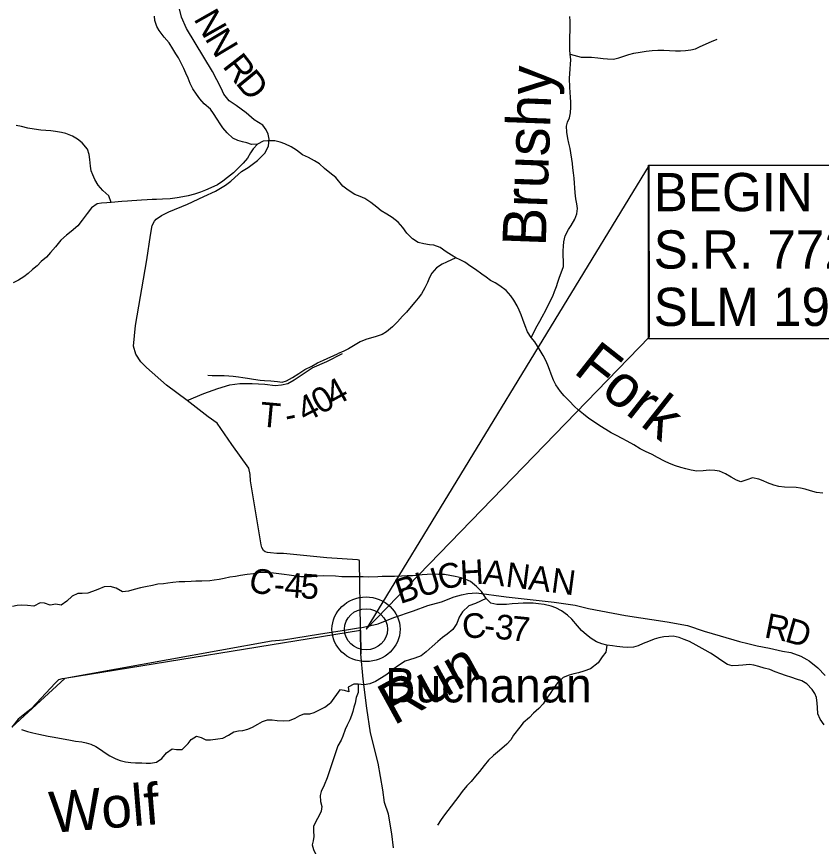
# Model space of a CAD drawing. Extents: x -139 to 835, y 0 to 440.
# Drawn here: x 183.8 to 242.7, y 229.6 to 290.4 of the extents above; entities that cross this region are included whole.
import ezdxf

# ---------------------------------------------------------------- set-up
doc = ezdxf.new("R2010")
doc.units = 0
for name, color, linetype in [('Default', 7, 'Continuous'), ('GM_X_County_Road', 7, 'Continuous'), ('GM_X_County_Road_Text', 7, 'Continuous'), ('GM_X_Major_River', 7, 'Continuous'), ('GM_X_Minor_River', 7, 'Continuous'), ('GM_X_Minor_River_Text', 7, 'Continuous'), ('GM_X_State_Route', 7, 'Continuous'), ('GM_X_Township_Road', 7, 'Continuous'), ('GM_X_Township_Road_Text', 7, 'Continuous'), ('GM_X_Unincorporated', 7, 'Continuous'), ('GM_X_Unincorporated_Location', 7, 'Continuous'), ('GM_X_Unincorporated_Text', 7, 'Continuous'), ('SH_Text', 7, 'Continuous')]:
    doc.layers.add(name, color=color, linetype=linetype)

msp = doc.modelspace()

# ---------------------------------------------------------------- linework, layer by layer
at = {"layer": 'Default'}
for p, q in [((208.941, 245.405), (187.302, 241.902)), ((208.941, 245.405), (187.302, 241.902)), ((208.941, 245.405), (208.975, 243.698)), ((187.302, 241.902), (183.419, 238.323))]:
    msp.add_line(p, q, dxfattribs=at)
at = {"layer": 'GM_X_County_Road'}
for points in [[(208.938, 245.595), (208.877, 250.478), (208.839, 250.551), (208.723, 250.588), (206.492, 250.734), (203.319, 251.036), (202.825, 251.041), (202.369, 251.082), (202.141, 251.108), (201.964, 251.171), (201.852, 251.256), (201.727, 251.475), (201.679, 251.668), (200.909, 256.37), (200.863, 256.816), (200.78, 257.288), (199.532, 259.026), (198.46, 260.594), (197.794, 261.06), (196.274, 262.258), (194.741, 263.36), (193.285, 264.655), (192.872, 265.081), (192.498, 265.64), (192.34, 266.233), (192.471, 267.728), (193.312, 272.556), (193.573, 274.351), (193.708, 275.049), (193.876, 275.373), (194.005, 275.517), (194.375, 275.802), (194.911, 276.062), (196.298, 276.614), (197.484, 277.181), (198.325, 277.582), (199.065, 278.02), (199.448, 278.306), (199.755, 278.568), (200.229, 279.009), (200.739, 279.293), (201.417, 279.817), (201.955, 280.354), (202.227, 280.87), (202.259, 281.376), (202.199, 281.739), (202.051, 282.066), (201.789, 282.395), (201.172, 282.787), (200.582, 283.3), (199.853, 283.839), (199.338, 284.182), (198.95, 284.669), (198.753, 285.105), (198.107, 286.33), (196.217, 289.475), (195.846, 290.323), (195.653, 291.121)], [(208.938, 245.595), (210.245, 245.901), (211.378, 246.356), (212.816, 246.847), (213.873, 247.242), (214.866, 247.516), (215.796, 247.864), (216.33, 248.019), (216.814, 248.126), (217.437, 248.161), (219.611, 247.877), (223.132, 247.481), (224.657, 247.259), (225.648, 247.027), (227.453, 246.684), (228.342, 246.513), (231.393, 246.046), (232.892, 245.764), (234.112, 245.35), (235.281, 245.021), (236.691, 244.607), (237.288, 244.461), (237.974, 244.278), (238.876, 244.106), (239.829, 243.898), (240.439, 243.788), (241.176, 243.52), (241.62, 243.29), (241.798, 243.193), (242.419, 242.661), (242.964, 242.104)]]:
    msp.add_lwpolyline(points, dxfattribs=at)
at = {"layer": 'GM_X_Major_River'}
for points in [[(207.131, 249.374), (206.234, 249.418), (205.828, 249.375), (205.358, 249.344), (205.04, 249.336), (204.571, 249.341), (203.734, 249.447), (203.354, 249.5), (202.784, 249.591), (202.379, 249.632), (202.011, 249.648), (201.516, 249.63), (201.121, 249.562), (200.663, 249.495), (200.168, 249.44), (199.811, 249.372), (199.392, 249.305), (198.972, 249.225), (198.603, 249.145), (198.234, 249.089), (197.916, 249.044), (197.332, 249.027), (196.888, 249.02), (196.557, 248.988), (196.087, 248.981), (195.681, 248.962), (195.224, 248.918), (194.855, 248.862), (194.524, 248.83), (194.105, 248.787), (193.736, 248.707), (193.201, 248.592), (192.858, 248.524), (192.387, 248.42), (191.966, 248.293), (191.534, 248.249), (191.068, 248.508), (190.625, 248.634), (190.193, 248.603), (189.734, 248.403), (189.338, 248.251), (188.981, 248.134), (188.588, 248.127), (188.27, 248.118), (187.849, 247.93), (187.463, 247.548), (187.04, 247.252), (186.648, 247.329), (186.241, 247.273), (185.824, 247.41), (185.494, 247.426), (185.034, 247.178), (184.578, 247.244), (184.147, 247.249), (183.829, 247.241), (183.486, 247.172)], [(234.565, 243.743), (234.185, 243.975), (233.527, 244.342), (233.019, 244.599), (232.639, 244.758), (232.271, 244.906), (231.839, 244.981), (231.521, 244.971), (231.151, 244.949), (230.794, 244.879), (230.437, 244.761), (230.028, 244.607), (229.633, 244.453), (229.275, 244.274), (228.93, 244.18), (228.497, 244.171), (228.141, 244.174), (227.709, 244.237), (227.391, 244.275), (226.971, 244.339), (226.603, 244.438), (226.222, 244.585), (225.83, 244.817), (225.488, 245.085), (225.122, 245.413), (224.832, 245.741), (224.416, 246.227), (224.1, 246.531), (223.657, 246.847), (223.239, 247.067), (222.909, 247.178), (222.401, 247.314), (221.981, 247.354), (221.574, 247.405), (221.244, 247.419), (220.849, 247.398), (220.492, 247.376), (220.059, 247.355), (219.626, 247.321), (219.244, 247.312), (218.926, 247.302), (218.494, 247.402), (218.153, 247.754), (217.801, 248.263), (217.448, 248.64), (216.993, 248.993), (216.65, 249.152), (216.32, 249.263), (215.875, 249.363), (215.481, 249.438), (215.087, 249.501), (214.655, 249.516), (214.248, 249.543), (213.84, 249.497), (213.471, 249.488), (213.089, 249.442), (212.745, 249.42), (212.363, 249.411), (211.943, 249.39), (211.446, 249.357), (211.013, 249.36), (210.529, 249.351), (210.211, 249.329), (209.498, 249.31), (209.155, 249.324), (208.747, 249.339), (208.327, 249.33), (207.576, 249.335), (207.131, 249.374)], [(242.885, 238.497), (242.595, 238.909), (242.433, 239.297), (242.399, 239.768), (242.376, 240.093), (242.316, 240.492), (242.204, 240.795), (242.002, 241.098), (241.611, 241.499), (241.257, 241.718), (240.85, 241.854), (240.508, 241.965), (240.063, 242.101), (239.708, 242.236), (239.289, 242.383), (238.896, 242.543), (238.502, 242.654), (238.096, 242.778), (237.74, 242.877), (237.41, 242.927), (236.926, 242.87), (236.607, 242.836), (236.162, 242.827), (235.819, 242.926), (235.312, 243.231), (234.971, 243.487), (234.565, 243.743)]]:
    msp.add_lwpolyline(points, dxfattribs=at)
at = {"layer": 'GM_X_Minor_River'}
for points in [[(201.398, 281.002), (200.966, 280.99), (200.622, 281.111), (200.305, 281.184), (199.962, 281.292), (199.606, 281.462), (199.187, 281.848), (198.882, 282.211), (198.666, 282.513), (198.45, 282.851), (198.183, 283.262), (197.967, 283.576), (197.497, 283.963), (197.192, 284.337), (196.951, 284.664), (196.684, 285.062), (196.481, 285.461), (196.329, 285.836), (196.164, 286.222), (196.024, 286.549), (195.808, 286.983), (195.618, 287.334), (195.427, 287.636), (195.224, 287.986), (194.945, 288.433), (194.589, 288.856), (194.221, 289.328), (194.043, 289.63), (193.904, 290.064), (193.878, 290.379)], [(221.438, 266.858), (221.889, 267.719), (222.076, 268.046), (222.239, 268.373), (222.514, 268.859), (222.689, 269.222), (223.014, 269.876), (223.138, 270.215), (223.287, 270.603), (223.386, 270.917), (223.51, 271.28), (223.635, 271.583), (223.796, 272.055), (223.805, 272.393), (223.788, 272.9), (223.785, 273.213), (223.808, 273.551), (223.83, 273.853), (223.928, 274.3), (224.165, 274.761), (224.366, 275.064), (224.642, 275.513), (224.791, 275.901), (224.826, 276.311), (224.784, 276.648), (224.717, 277.022), (224.662, 277.456), (224.634, 277.805), (224.605, 278.167), (224.576, 278.529), (224.534, 278.914), (224.493, 279.288), (224.464, 279.601), (224.423, 279.915), (224.355, 280.384), (224.289, 280.697), (224.196, 281.095), (224.117, 281.432), (224.049, 281.902), (224.032, 282.324), (224.093, 282.626), (224.243, 282.953), (224.316, 283.304), (224.35, 283.714), (224.347, 284.112), (224.318, 284.425), (224.289, 284.823), (224.26, 285.173), (224.254, 285.848), (224.264, 286.162), (224.299, 286.536), (224.321, 286.874), (224.331, 287.2), (224.289, 287.598), (224.261, 287.911), (224.258, 288.213), (224.267, 288.599), (224.277, 288.901), (224.286, 289.311), (224.282, 289.697), (224.292, 290.011), (224.276, 290.36)], [(224.289, 287.598), (225.106, 287.376), (225.525, 287.38), (225.856, 287.395), (226.315, 287.339), (226.71, 287.282), (227.028, 287.261), (227.474, 287.241), (227.855, 287.329), (228.21, 287.453), (228.578, 287.577), (228.959, 287.665), (229.429, 287.741), (229.861, 287.818), (230.306, 287.87), (230.7, 287.886), (231.159, 287.89), (231.566, 287.869), (232.012, 287.849), (232.368, 287.853), (232.737, 287.868), (233.131, 287.908), (233.474, 287.983), (233.816, 288.167), (234.627, 288.537), (235.045, 288.709)], [(190.693, 276.739), (190.541, 277.222), (190.083, 277.609), (189.753, 278.008), (189.499, 278.43), (189.347, 278.769), (189.245, 279.071), (189.182, 279.397), (189.144, 279.892), (189.094, 280.255), (188.967, 280.654), (188.573, 281.113), (188.23, 281.379), (187.874, 281.608), (187.391, 281.802), (187.061, 281.874), (186.629, 281.947), (186.285, 281.995), (185.917, 282.007), (185.548, 282.043), (185.053, 282.104), (184.608, 282.177), (184.138, 282.297), (183.756, 282.382)], [(207.154, 278.585), (206.709, 278.923), (206.316, 279.238), (205.947, 279.576), (205.579, 279.805), (205.147, 280.035), (204.715, 280.241), (204.27, 280.567), (203.863, 280.821), (203.406, 281.05), (203.076, 281.159), (202.669, 281.256), (202.173, 281.268), (201.83, 281.244), (201.398, 281.002), (201.092, 280.676), (200.889, 280.374), (200.673, 280), (200.355, 279.625), (200.075, 279.323), (199.655, 278.912), (199.223, 278.574), (198.867, 278.308), (198.473, 278.043), (197.99, 277.813), (197.608, 277.656), (197.239, 277.511), (196.794, 277.354), (196.337, 277.221), (195.955, 277.161), (195.536, 277.076), (195.028, 277.016), (194.468, 276.992), (194.023, 276.968), (193.706, 276.956), (193.337, 276.932), (192.93, 276.908), (192.587, 276.896), (192.218, 276.871), (191.901, 276.847), (191.481, 276.811), (190.693, 276.739), (190.375, 276.715), (189.994, 276.691), (189.664, 276.654), (189.257, 276.34), (188.939, 275.93), (188.582, 275.446), (188.264, 275.023), (187.781, 274.625), (187.425, 274.359), (187.018, 273.973), (186.624, 273.489), (186.255, 273.079), (185.963, 272.752), (185.568, 272.414), (185.289, 272.112), (184.945, 271.834), (184.615, 271.544), (184.297, 271.291), (183.928, 271.061), (183.521, 270.868)], [(208.935, 277.18), (208.539, 277.333), (208.053, 277.654), (207.656, 277.928), (207.154, 278.585)], [(242.796, 255.471), (242.325, 255.515), (241.891, 255.632), (241.483, 255.749), (241.151, 255.83), (240.833, 255.875), (239.993, 255.892), (239.559, 255.948), (239.202, 256.054), (238.742, 256.23), (238.423, 256.36), (238.104, 256.478), (237.644, 256.594), (237.226, 256.434), (236.795, 256.297), (236.475, 256.415), (236.066, 256.628), (235.657, 256.866), (235.222, 257.067), (234.891, 257.112), (234.458, 257.144), (234.038, 257.104), (233.568, 257.076), (233.16, 257.157), (232.752, 257.249), (232.382, 257.33), (231.999, 257.46), (231.564, 257.625), (231.206, 257.802), (230.695, 258.075), (230.286, 258.289), (229.813, 258.514), (229.429, 258.715), (228.943, 258.988), (228.47, 259.261), (228.111, 259.475), (227.689, 259.688), (227.306, 259.89), (226.896, 260.128), (226.474, 260.389), (226.064, 260.651), (225.667, 260.937), (225.27, 261.235), (224.911, 261.533), (224.59, 261.82), (224.243, 262.203), (223.858, 262.585), (223.575, 262.908), (223.252, 263.388), (223.071, 263.736), (222.914, 264.181), (222.784, 264.506), (222.653, 264.842), (222.523, 265.167), (222.329, 265.539), (222.031, 266.031), (221.696, 266.547), (221.438, 266.858), (221.18, 267.278), (220.998, 267.711), (220.828, 268.18), (220.698, 268.528), (220.567, 268.853), (220.412, 269.177), (220.179, 269.585), (219.947, 269.897), (219.6, 270.292), (219.138, 270.649), (218.793, 270.863), (218.473, 271.041), (218.14, 271.268), (217.82, 271.494), (217.358, 271.828), (217.013, 272.054), (216.577, 272.363), (216.245, 272.541), (215.925, 272.695), (215.605, 272.885), (215.221, 273.123), (214.785, 273.445), (214.326, 273.609), (214.007, 273.655), (213.587, 273.711), (213.166, 273.816), (212.743, 274.078), (212.332, 274.508), (212.036, 274.904), (211.701, 275.311), (211.278, 275.633), (210.869, 275.882), (210.472, 276.144), (210.151, 276.394), (209.715, 276.74), (209.267, 277.026), (208.935, 277.18)], [(215.925, 272.695), (215.254, 272.363), (214.924, 272.216), (214.506, 271.958), (214.166, 271.569), (213.991, 271.242), (213.842, 270.879), (213.655, 270.491), (213.417, 270.066), (213.178, 269.738), (212.926, 269.435), (212.662, 269.119), (212.309, 268.717), (212.032, 268.413), (211.667, 267.999), (211.301, 267.634), (210.859, 267.268), (210.53, 267.084), (210.098, 266.924), (209.337, 266.724), (208.931, 266.551), (208.07, 266.036), (207.729, 265.852), (207.272, 265.667)], [(197.778, 264.112), (198.096, 264.076), (198.96, 264.075), (199.304, 264.063), (199.634, 264.039), (200.015, 263.979), (200.346, 263.93), (200.689, 263.87), (201.121, 263.797), (201.604, 263.737), (201.922, 263.713), (202.379, 263.676), (202.862, 263.628), (203.205, 263.592), (203.536, 263.676), (203.968, 263.918), (204.439, 264.232), (204.871, 264.51), (205.392, 264.763), (205.812, 265.005), (206.244, 265.21), (207.272, 265.667)], [(218.153, 247.754), (217.354, 247.385), (216.885, 247.212), (216.405, 246.785), (216.18, 246.385), (216.006, 245.913), (215.717, 245.488), (215.288, 245.146), (214.959, 244.902), (214.618, 244.609), (214.189, 244.243), (213.76, 243.841), (213.393, 243.561), (212.924, 243.387), (212.543, 243.263), (212.213, 243.152), (211.72, 242.834), (211.303, 242.54), (210.886, 242.187), (210.481, 241.929), (210.051, 241.672), (209.632, 241.512), (209.213, 241.435), (208.78, 241.468), (208.462, 241.477), (208.044, 241.268), (208.098, 240.918), (207.779, 241.024), (207.448, 241.069), (206.764, 240.103)], [(226.971, 244.339), (226.906, 243.817), (226.642, 243.488), (226.341, 243.051), (225.785, 242.612), (225.303, 242.427), (224.897, 242.302), (224.567, 242.227), (224.224, 242.139), (223.78, 241.954), (223.376, 241.565), (223.062, 241.139), (222.836, 240.8), (222.573, 240.423), (222.322, 240.035), (222.006, 239.706), (221.602, 239.365), (221.313, 239.036), (220.858, 238.658), (220.607, 238.318), (220.141, 237.747), (219.953, 237.407), (219.651, 237.091), (219.133, 236.616), (218.691, 236.25), (218.325, 235.908), (217.998, 235.531), (217.658, 235.082), (217.356, 234.741), (217.041, 234.352), (216.739, 234.024), (216.399, 233.611), (216.135, 233.282), (215.896, 232.955), (215.582, 232.554), (215.33, 232.226), (215.091, 231.922), (214.853, 231.57), (214.589, 231.157)], [(208.78, 241.468), (208.773, 240.876), (208.636, 240.489), (208.551, 240.09), (208.465, 239.788), (208.391, 239.485), (208.279, 239.183), (208.18, 238.868), (207.968, 238.468), (207.818, 238.153), (207.657, 237.681), (207.545, 237.379), (207.282, 236.966), (206.506, 234.617)], [(184.138, 238.161), (184.57, 238.004), (184.964, 237.907), (185.409, 237.822), (185.752, 237.738), (186.095, 237.665), (186.527, 237.592), (186.921, 237.52), (187.341, 237.459), (187.735, 237.375), (188.078, 237.314), (188.548, 237.254), (188.879, 237.193), (189.209, 237.085), (189.577, 236.915), (189.92, 236.686), (190.264, 236.456), (190.607, 236.239), (191.051, 236.009), (191.369, 235.888), (191.738, 235.791), (192.132, 235.743), (192.487, 235.707), (192.945, 235.719), (193.263, 235.695), (193.581, 235.694), (194.013, 235.767), (194.407, 236.033), (194.738, 236.455), (195.157, 236.733), (195.488, 236.697), (195.894, 236.697), (196.34, 237.132), (196.556, 237.434), (196.937, 237.676), (197.28, 237.579), (197.636, 237.398), (197.979, 237.397), (198.5, 237.482), (198.882, 237.518), (199.276, 237.748), (199.683, 237.977), (200.026, 238.05), (200.344, 238.086), (200.713, 238.182), (201.056, 238.327), (201.437, 238.545), (201.781, 238.75), (202.149, 238.859), (202.48, 238.859), (202.848, 238.822), (203.331, 238.786), (203.751, 238.81), (204.17, 238.979), (204.501, 239.185), (204.819, 239.293), (205.251, 239.305), (205.569, 239.402), (205.988, 239.619), (206.344, 239.801), (206.764, 240.103)], [(206.506, 234.617), (206.29, 234.086), (206.074, 233.626), (205.985, 233.324), (206.01, 232.889), (206.111, 232.527), (206.06, 232.177), (205.92, 231.862), (205.678, 231.427), (205.5, 231.065), (205.5, 230.727), (205.538, 230.328), (205.474, 230.014), (205.423, 229.712), (205.512, 229.374), (205.652, 229.059), (205.702, 228.709), (205.689, 228.31), (205.88, 227.863), (206.083, 227.549), (206.388, 227.138), (206.604, 226.715)]]:
    msp.add_lwpolyline(points, dxfattribs=at)
at = {"layer": 'GM_X_State_Route'}
for points in [[(208.941, 245.405), (208.938, 245.595), (207.927, 245.438), (205.866, 245.113), (203.319, 244.692), (202.438, 244.616), (187.302, 241.902), (187.122, 241.867), (186.84, 241.804), (186.591, 241.556), (185.239, 240.091), (184.819, 239.642), (184.494, 239.409), (183.894, 238.904), (183.419, 238.323)], [(211.376, 229.495), (211.239, 230.513), (210.986, 231.969), (210.703, 232.821), (210.575, 233.73), (210.246, 235.695), (209.67, 237.919), (209.414, 239.713), (209.14, 241.833), (208.975, 243.698), (208.941, 245.405)]]:
    msp.add_lwpolyline(points, dxfattribs=at)
at = {"layer": 'GM_X_Township_Road'}
msp.add_lwpolyline([(196.274, 262.258), (197.484, 262.752), (198.502, 263.115), (199.379, 263.383), (200.128, 263.484), (201.015, 263.486), (201.953, 263.44), (202.699, 263.336), (203.156, 263.391), (203.626, 263.482), (204.085, 263.755), (205.413, 264.634), (206.496, 265.105), (207.643, 265.684)], dxfattribs=at)
at = {"layer": 'GM_X_Unincorporated'}
for major_axis in [(2.493, 0), (1.581, 0)]:
    msp.add_ellipse((209.354, 245.496), major_axis=major_axis, ratio=0.948307, dxfattribs=at)
at = {"layer": 'GM_X_Unincorporated_Location'}
msp.add_line((209.354, 245.496), (209.354, 245.496), dxfattribs=at)
at = {"layer": 'SH_Text'}
for points in [[(209.354, 245.496), (230.099, 266.9), (230.068, 279.465)], [(230.034, 279.464), (258.605, 279.464), (258.605, 266.754), (230.034, 266.754)]]:
    msp.add_lwpolyline(points, close=True, dxfattribs=at)

# ---------------------------------------------------------------- texts
at = {"layer": 'GM_X_County_Road_Text'}
for s, height, rotation, p in [('N', 1.895, 299.54706, (196.7, 290.196)), ('N', 1.893, 300.94241, (197.518, 288.755)), ('R', 1.886, 307.78619, (198.792, 286.711)), ('D', 1.884, 309.3678, (199.753, 285.473)), ('C', 1.821, 16.88355, (214.909, 248.298)), ('H', 1.806, 3.02803, (216.273, 248.728)), ('A', 1.808, 353.27413, (217.856, 248.819)), ('N', 1.808, 352.90462, (219.515, 248.624)), ('C', 1.815, 346.72234, (200.66, 248.318)), ('U', 1.821, 17.13144, (213.318, 247.807)), ('A', 1.809, 352.89776, (221.176, 248.417)), ('N', 1.809, 352.39805, (222.833, 248.21)), ('4', 1.807, 355.86459, (203.339, 247.866)), ('5', 1.807, 355.91221, (204.511, 247.781)), ('B', 1.823, 17.94275, (211.845, 247.33)), ('-', 1.806, 357.13869, (202.57, 247.904)), ('C', 1.808, 5.85041, (216.48, 244.773)), ('3', 1.808, 353.54908, (218.727, 244.826)), ('7', 1.808, 354.2893, (219.92, 244.691)), ('R', 1.813, 348.72579, (238.436, 244.918)), ('D', 1.819, 344.06365, (239.925, 244.623)), ('-', 1.809, 352.43497, (217.911, 244.934))]:
    msp.add_text(s, height=height, rotation=rotation, dxfattribs=at).set_placement(p)
at = {"layer": 'GM_X_Minor_River_Text'}
for s, height, rotation, p in [('Brushy', 3.1736, 87.89106, (222.499, 273.495)), ('Fork', 3.1052, 321.78565, (224.452, 264.317)), ('Run', 3.0727, 28.72623, (211.378, 238.424)), ('Wolf', 3.0115, 4.71387, (186.299, 230.58))]:
    msp.add_text(s, height=height, rotation=rotation, dxfattribs=at).set_placement(p)
at = {"layer": 'GM_X_Township_Road_Text'}
for s, height, rotation, p in [('4', 1.844, 29.09336, (207.022, 261.754)), ('0', 1.846, 29.77112, (206.023, 261.182)), ('4', 1.84, 27.05061, (204.902, 260.607)), ('T', 1.807, 354.75565, (201.535, 260.356)), ('-', 1.813, 11.51418, (203.589, 260.26))]:
    msp.add_text(s, height=height, rotation=rotation, dxfattribs=at).set_placement(p)
at = {"layer": 'GM_X_Unincorporated_Text'}
msp.add_text('Buchanan', height=2.5099, rotation=0.00001, dxfattribs=at).set_placement((210.749, 240.142))
at = {"layer": 'SH_Text'}
for s, p in [('BEGIN PROJECT', (230.407, 276.104)), ('S.R. 772             ', (230.407, 271.904)), ('SLM 19.00         ', (230.407, 267.704))]:
    msp.add_text(s, height=2.79999, dxfattribs=at).set_placement(p)

doc.saveas('drawing.dxf')
